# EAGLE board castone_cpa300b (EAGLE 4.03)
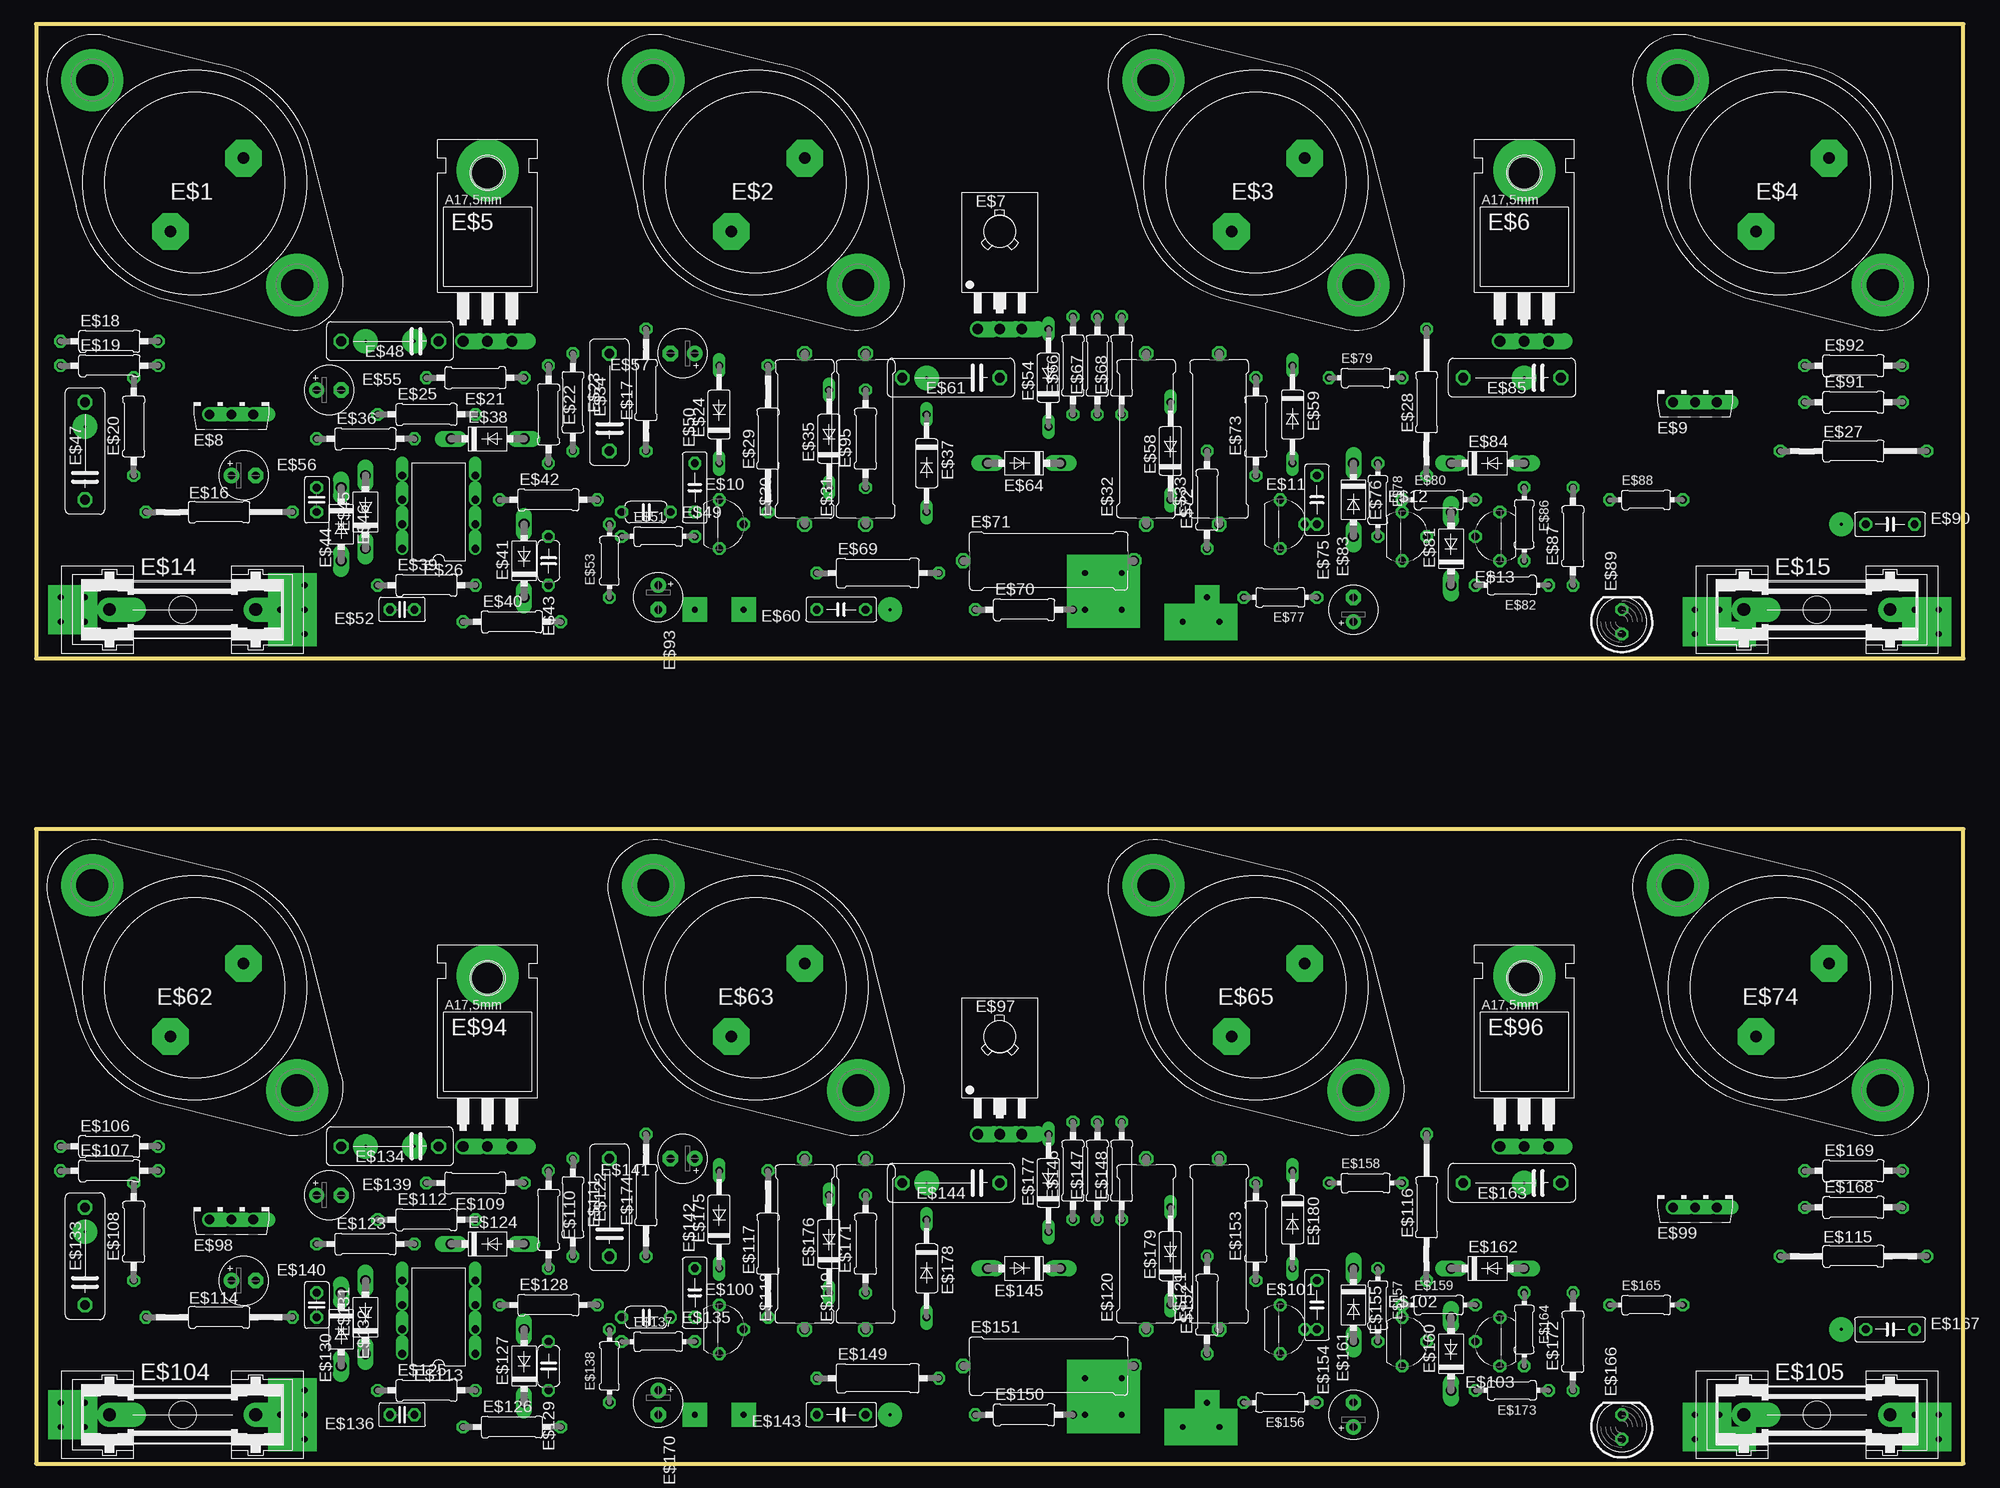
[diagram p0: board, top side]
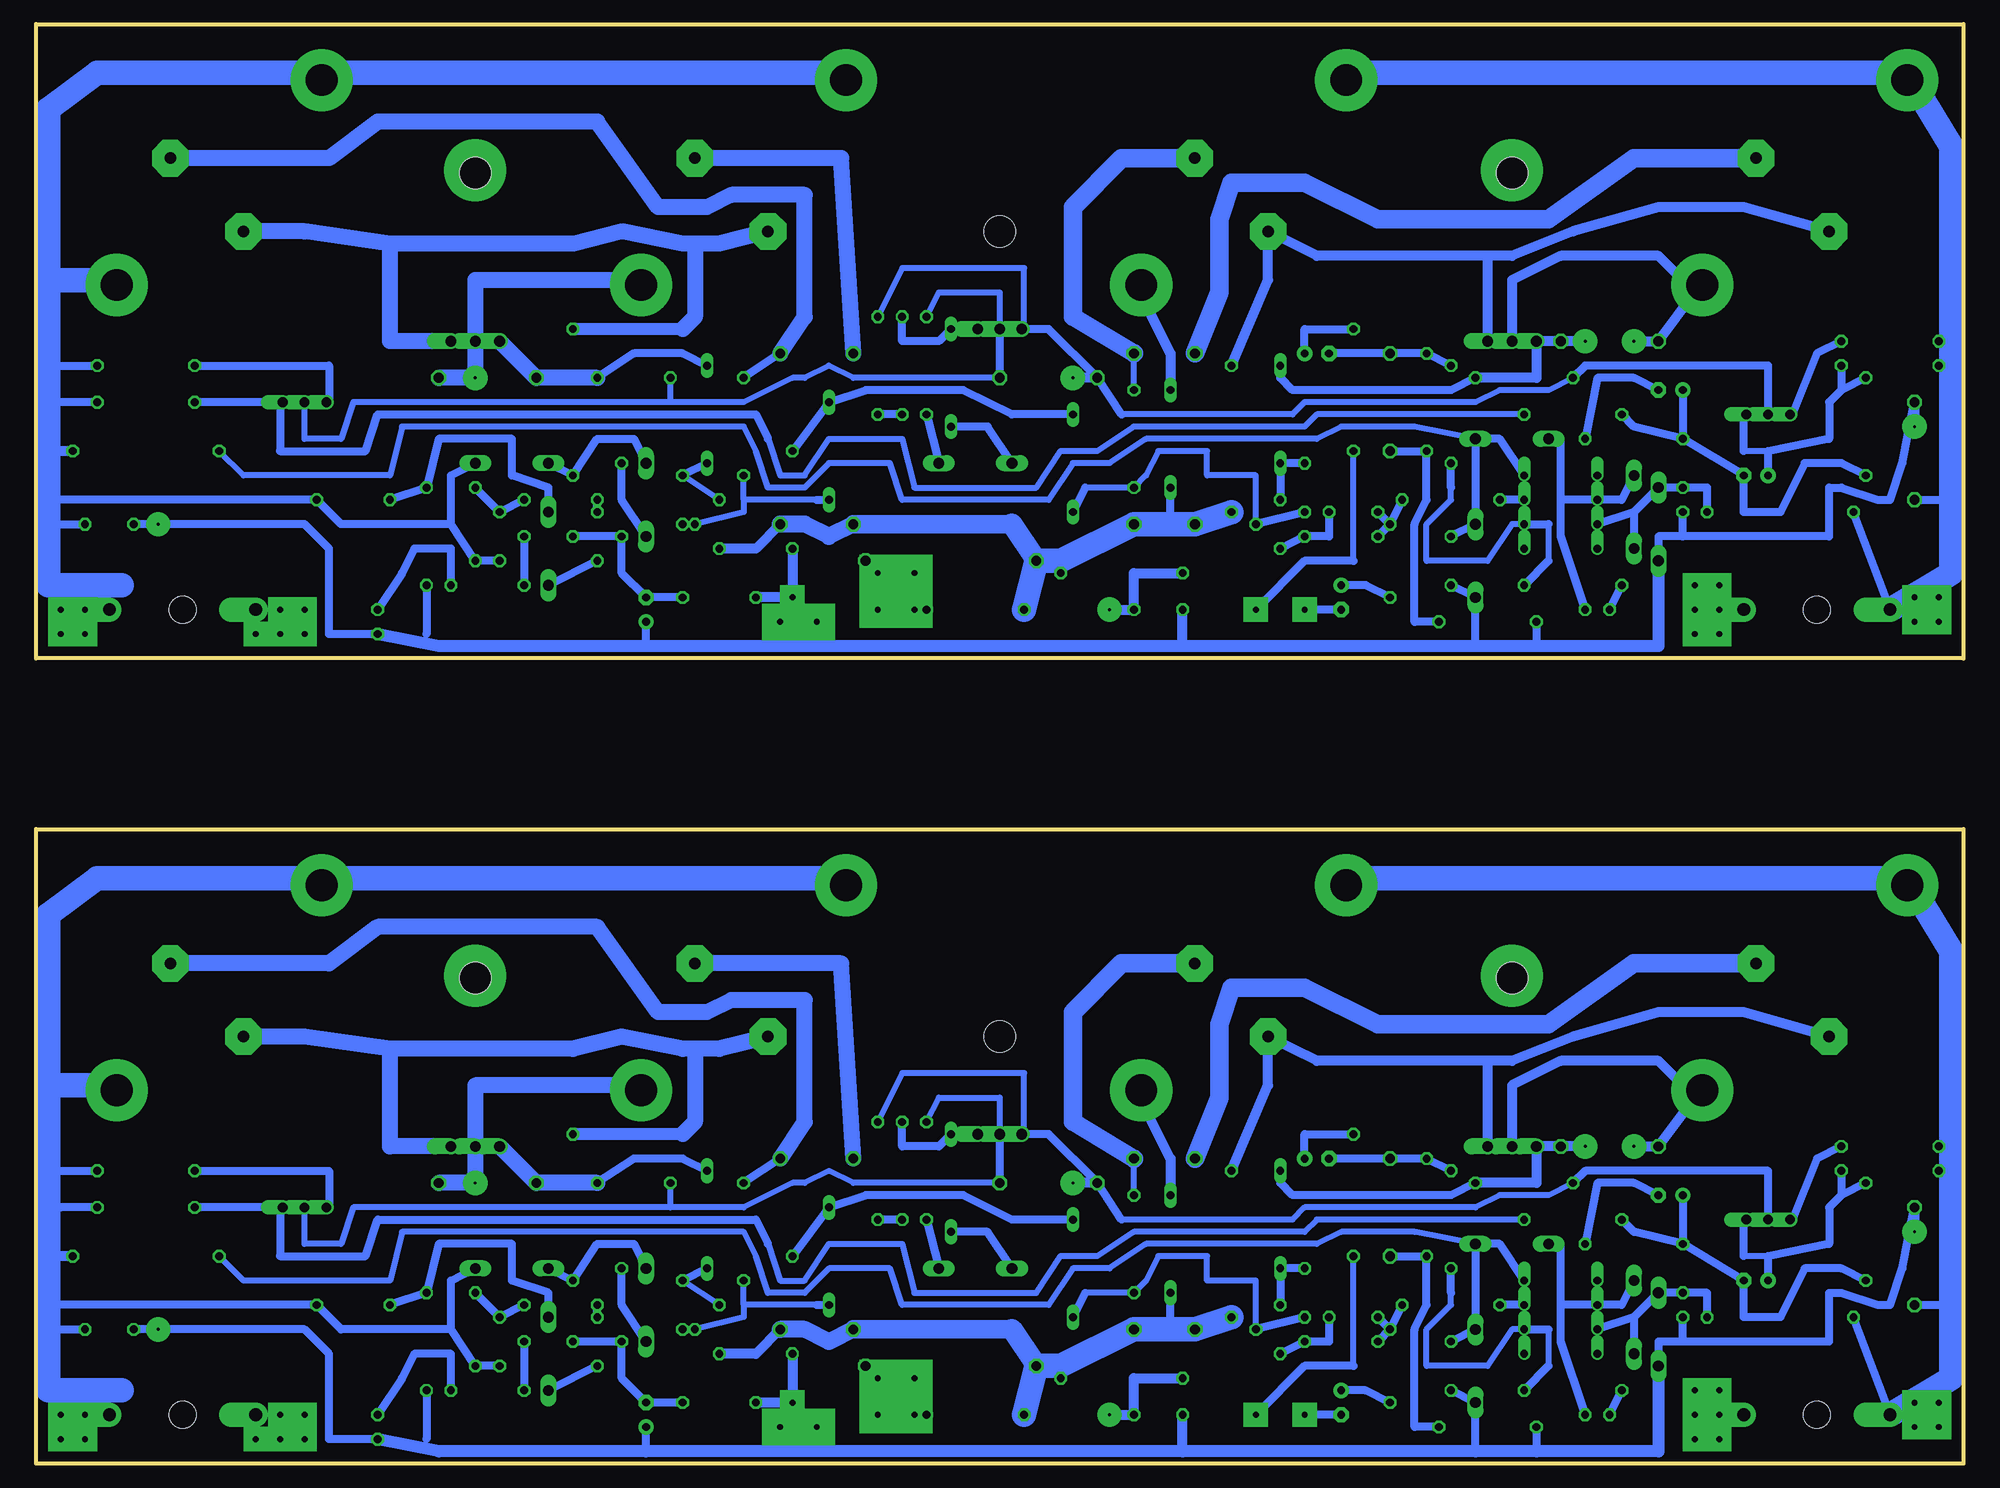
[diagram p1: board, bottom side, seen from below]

Size 200.66 x 149.86 mm. Coordinates in mm from the lower left corner, seen from the top.
Outline: 0,83.82 200.66,83.82 200.66,149.86 0,149.86 0,83.82
Outline: 0,0 200.66,0 200.66,66.04 0,66.04 0,0
Copper layers used: Bottom

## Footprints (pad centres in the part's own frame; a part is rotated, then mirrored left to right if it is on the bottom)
TO3/A = drill 1.194 pad 3.81 octagon: B 2.54,5.08; E -5.08,-2.54 | drill 3.302 pad 6.477 round: C 10.668,-10.668; C/ -10.668,10.668
TO220 = drill 1.118 offset: 1 -2.54,-6.35; 2 0,-6.35; 3 2.54,-6.35 | hole 3.302: 0,11.176
TO126 = drill 1.118 offset: 1 -2.286,-5.08; 2 0,-5.08; 3 2.286,-5.08 | hole 3.302: 0,5.08
TO126V = drill 1.016 offset: 1 -2.286,-1.27; 2 0,-1.27; 3 2.286,-1.27
TO92L = drill 0.813 octagon: 1 0,-2.54; 2 2.54,0; 3 0,2.54
GSH15 = drill 1.321 pad 2.54 offset: 1 -7.62,0; 2 7.62,0 | hole 2.794: 0,0
0207/15 = drill 0.813 octagon: 1 -7.62,0; 2 7.62,0
0207/12 = drill 0.813 octagon: 1 -6.35,0; 2 6.35,0
0207/10 = drill 0.813 octagon: 1 -5.08,0; 2 5.08,0
C2992 = drill 0.813 long: A 5.08,0; C -5.08,0
DIL08 = drill 0.813 offset: 1 -3.81,-3.81; 2 -1.27,-3.81; 3 1.27,-3.81; 4 3.81,-3.81; 5 3.81,3.81; 6 1.27,3.81; 7 -1.27,3.81; 8 -3.81,3.81
0617/17 = drill 1.016 octagon: 1 -8.89,0; 2 8.89,0
C102-043X133 = drill 1.016 octagon: 1 -5.08,0; 2 5.08,0
DO41-7 = drill 1.118 long: A 3.81,0; C -3.81,0
C050-024X044 = drill 0.813 octagon: 1 -2.54,0; 2 2.54,0
C025-025X050 = drill 0.813 octagon: 1 -1.27,0; 2 1.27,0
C050-025X075 = drill 0.813 octagon: 1 -2.54,0; 2 2.54,0
0204/7 = drill 0.813 octagon: 1 -3.81,0; 2 3.81,0
E2,5-5 = drill 0.813 pad 1.6 round: + -1.27,0 | drill 0.813 pad 1.6 octagon: - 1.27,0
0309/12 = drill 0.813 octagon: 1 -6.35,0; 2 6.35,0
LED5MM = drill 0.813 octagon: A -1.27,0; K 1.27,0

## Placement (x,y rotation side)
E$1  [TO3/A]  16.51,133.35 180 top
E$2  [TO3/A]  74.93,133.35 180 top
E$3  [TO3/A]  127,133.35 180 top
E$4  [TO3/A]  181.61,133.35 180 top
E$5  [TO220]  46.99,123.19 0 top
E$6  [TO220]  154.94,123.19 0 top
E$7  [TO126]  100.33,123.19 0 top
E$8  [TO126V]  20.32,110.49 0 top
E$9  [TO126V]  172.72,111.76 0 top
E$10  [TO92L]  71.12,97.79 0 top
E$11  [TO92L]  129.54,97.79 0 top
E$12  [TO92L]  142.24,96.52 0 top
E$13  [TO92L]  152.4,96.52 180 top
E$14  [GSH15]  15.24,88.9 0 top
E$15  [GSH15]  185.42,88.9 0 top
E$16  [0207/15]  19.05,99.06 0 top
E$17  [0207/12]  63.5,111.76 90 top
E$18  [0207/10]  7.62,116.84 0 top
E$19  [0207/10]  7.62,114.3 0 top
E$20  [0207/10]  10.16,107.95 90 top
E$21  [0207/10]  45.72,113.03 180 top
E$22  [0207/10]  53.34,109.22 270 top
E$23  [0207/10]  55.88,110.49 270 top
E$24  [C2992]  71.12,109.22 90 top
E$25  [0207/10]  40.64,109.22 0 top
E$26  [DIL08]  41.91,99.06 90 top
E$27  [0207/15]  189.23,105.41 0 top
E$28  [0207/15]  144.78,110.49 90 top
E$29  [0207/15]  76.2,106.68 90 top
E$30  [0617/17]  80.01,106.68 90 top
E$31  [0617/17]  86.36,106.68 90 top
E$32  [0617/17]  115.57,106.68 90 top
E$33  [0617/17]  123.19,106.68 90 top
E$34  [C102-043X133]  59.69,110.49 90 top
E$35  [C2992]  82.55,106.68 90 top
E$36  [0207/10]  34.29,106.68 0 top
E$37  [C2992]  92.71,104.14 270 top
E$38  [DO41-7]  46.99,106.68 0 top
E$39  [0207/10]  40.64,91.44 0 top
E$40  [0207/10]  49.53,87.63 0 top
E$41  [DO41-7]  50.8,93.98 90 top
E$42  [0207/10]  53.34,100.33 0 top
E$43  [C050-024X044]  53.34,93.98 270 top
E$44  [C025-025X050]  29.21,100.33 270 top
E$45  [DO41-7]  34.29,99.06 90 top
E$46  [DO41-7]  31.75,97.79 270 top
E$47  [C102-043X133]  5.08,105.41 90 top
E$48  [C102-043X133]  36.83,116.84 180 top
E$49  [C050-024X044]  63.5,99.06 0 top
E$50  [C050-025X075]  68.58,101.6 90 top
E$51  [0204/7]  64.77,96.52 0 top
E$52  [C025-025X050]  38.1,88.9 180 top
E$53  [0204/7]  59.69,93.98 90 top
E$54  [C2992]  105.41,113.03 90 top
E$55  [E2,5-5]  30.48,111.76 0 top
E$56  [E2,5-5]  21.59,102.87 0 top
E$57  [E2,5-5]  67.31,115.57 180 top
E$58  [C2992]  118.11,105.41 90 top
E$59  [C2992]  130.81,109.22 270 top
E$60  [C050-025X075]  83.82,88.9 180 top
E$61  [C102-043X133]  95.25,113.03 180 top
E$62  [TO3/A]  16.51,49.53 180 top
E$63  [TO3/A]  74.93,49.53 180 top
E$64  [DO41-7]  102.87,104.14 180 top
E$65  [TO3/A]  127,49.53 180 top
E$66  [0207/10]  107.95,114.3 90 top
E$67  [0207/10]  110.49,114.3 90 top
E$68  [0207/10]  113.03,114.3 90 top
E$69  [0309/12]  87.63,92.71 0 top
E$70  [0207/10]  102.87,88.9 0 top
E$71  [0617/17]  105.41,93.98 0 top
E$72  [0207/10]  121.92,100.33 90 top
E$73  [0207/10]  127,107.95 90 top
E$74  [TO3/A]  181.61,49.53 180 top
E$75  [C050-025X075]  133.35,100.33 270 top
E$76  [DO41-7]  137.16,100.33 270 top
E$77  [0204/7]  129.54,90.17 180 top
E$78  [0204/7]  139.7,100.33 270 top
E$79  [0204/7]  138.43,113.03 0 top
E$80  [0204/7]  146.05,100.33 0 top
E$81  [DO41-7]  147.32,95.25 90 top
E$82  [0204/7]  153.67,91.44 180 top
E$83  [E2,5-5]  137.16,88.9 90 top
E$84  [DO41-7]  151.13,104.14 0 top
E$85  [C102-043X133]  153.67,113.03 180 top
E$86  [0204/7]  154.94,97.79 270 top
E$87  [0207/10]  160.02,96.52 90 top
E$88  [0204/7]  167.64,100.33 0 top
E$89  [LED5MM]  165.1,87.63 90 top
E$90  [C050-025X075]  193.04,97.79 0 top
E$91  [0207/10]  189.23,110.49 0 top
E$92  [0207/10]  189.23,114.3 0 top
E$93  [E2,5-5]  64.77,90.17 270 top
E$94  [TO220]  46.99,39.37 0 top
E$95  [0207/10]  86.36,106.68 90 top
E$96  [TO220]  154.94,39.37 0 top
E$97  [TO126]  100.33,39.37 0 top
E$98  [TO126V]  20.32,26.67 0 top
E$99  [TO126V]  172.72,27.94 0 top
E$100  [TO92L]  71.12,13.97 0 top
E$101  [TO92L]  129.54,13.97 0 top
E$102  [TO92L]  142.24,12.7 0 top
E$103  [TO92L]  152.4,12.7 180 top
E$104  [GSH15]  15.24,5.08 0 top
E$105  [GSH15]  185.42,5.08 0 top
E$106  [0207/10]  7.62,33.02 0 top
E$107  [0207/10]  7.62,30.48 0 top
E$108  [0207/10]  10.16,24.13 90 top
E$109  [0207/10]  45.72,29.21 180 top
E$110  [0207/10]  53.34,25.4 270 top
E$111  [0207/10]  55.88,26.67 270 top
E$112  [0207/10]  40.64,25.4 0 top
E$113  [DIL08]  41.91,15.24 90 top
E$114  [0207/15]  19.05,15.24 0 top
E$115  [0207/15]  189.23,21.59 0 top
E$116  [0207/15]  144.78,26.67 90 top
E$117  [0207/15]  76.2,22.86 90 top
E$118  [0617/17]  80.01,22.86 90 top
E$119  [0617/17]  86.36,22.86 90 top
E$120  [0617/17]  115.57,22.86 90 top
E$121  [0617/17]  123.19,22.86 90 top
E$122  [C102-043X133]  59.69,26.67 90 top
E$123  [0207/10]  34.29,22.86 0 top
E$124  [DO41-7]  46.99,22.86 0 top
E$125  [0207/10]  40.64,7.62 0 top
E$126  [0207/10]  49.53,3.81 0 top
E$127  [DO41-7]  50.8,10.16 90 top
E$128  [0207/10]  53.34,16.51 0 top
E$129  [C050-024X044]  53.34,10.16 270 top
E$130  [C025-025X050]  29.21,16.51 270 top
E$131  [DO41-7]  34.29,15.24 90 top
E$132  [DO41-7]  31.75,13.97 270 top
E$133  [C102-043X133]  5.08,21.59 90 top
E$134  [C102-043X133]  36.83,33.02 180 top
E$135  [C050-024X044]  63.5,15.24 0 top
E$136  [C025-025X050]  38.1,5.08 180 top
E$137  [0204/7]  64.77,12.7 0 top
E$138  [0204/7]  59.69,10.16 90 top
E$139  [E2,5-5]  30.48,27.94 0 top
E$140  [E2,5-5]  21.59,19.05 0 top
E$141  [E2,5-5]  67.31,31.75 180 top
E$142  [C050-025X075]  68.58,17.78 90 top
E$143  [C050-025X075]  83.82,5.08 180 top
E$144  [C102-043X133]  95.25,29.21 180 top
E$145  [DO41-7]  102.87,20.32 180 top
E$146  [0207/10]  107.95,30.48 90 top
E$147  [0207/10]  110.49,30.48 90 top
E$148  [0207/10]  113.03,30.48 90 top
E$149  [0309/12]  87.63,8.89 0 top
E$150  [0207/10]  102.87,5.08 0 top
E$151  [0617/17]  105.41,10.16 0 top
E$152  [0207/10]  121.92,16.51 90 top
E$153  [0207/10]  127,24.13 90 top
E$154  [C050-025X075]  133.35,16.51 270 top
E$155  [DO41-7]  137.16,16.51 270 top
E$156  [0204/7]  129.54,6.35 180 top
E$157  [0204/7]  139.7,16.51 270 top
E$158  [0204/7]  138.43,29.21 0 top
E$159  [0204/7]  146.05,16.51 0 top
E$160  [DO41-7]  147.32,11.43 90 top
E$161  [E2,5-5]  137.16,5.08 90 top
E$162  [DO41-7]  151.13,20.32 0 top
E$163  [C102-043X133]  153.67,29.21 180 top
E$164  [0204/7]  154.94,13.97 270 top
E$165  [0204/7]  167.64,16.51 0 top
E$166  [LED5MM]  165.1,3.81 90 top
E$167  [C050-025X075]  193.04,13.97 0 top
E$168  [0207/10]  189.23,26.67 0 top
E$169  [0207/10]  189.23,30.48 0 top
E$170  [E2,5-5]  64.77,6.35 270 top
E$171  [0207/10]  86.36,22.86 90 top
E$172  [0207/10]  160.02,12.7 90 top
E$173  [0204/7]  153.67,7.62 180 top
E$174  [0207/12]  63.5,27.94 90 top
E$175  [C2992]  71.12,25.4 90 top
E$176  [C2992]  82.55,22.86 90 top
E$177  [C2992]  105.41,29.21 90 top
E$178  [C2992]  92.71,20.32 270 top
E$179  [C2992]  118.11,21.59 90 top
E$180  [C2992]  130.81,25.4 270 top

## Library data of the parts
E$1-E$13 E$62 E$63 E$65 E$74 E$94 E$96-E$103 = transistor-pnp
E$14 E$15 E$104 E$105 = fuse
E$16-E$23 E$25 E$27-E$34 E$36 E$39 E$40 E$42-E$44 E$47-E$53 E$55-E$57 E$60 E$61 E$66-E$73 E$75 E$77-E$80 E$82 E$83 E$85-E$88 E$90-E$93 E$95 E$106-E$112 E$114-E$123 E$125 E$126 E$128-E$130 E$133-E$144 E$146-E$154 E$156-E$159 E$161 E$163-E$165 E$167-E$174 = rcl
E$24 E$35 E$37 E$38 E$41 E$45 E$46 E$54 E$58 E$59 E$64 E$76 E$81 E$84 E$124 E$127 E$131 E$132 E$145 E$155 E$160 E$162 E$175-E$180 = diode
E$26 E$113 = dil
E$89 E$166 = led

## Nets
S$1: E$18.2
S$2: E$19.2 E$20.2 E$56.+
S$4: E$5.2 E$48.2
S$5: E$1.E E$30.2
S$6: E$35.A
S$7: E$2.E E$31.2 E$95.2
S$8: E$11.3 E$59.A E$75.1
S$9: E$16.2 E$26.7 E$44.1 E$45.C E$46.C
S$10: E$20.1 E$25.1 E$36.1 E$55.+ E$56.-
S$11: E$26.6 E$38.C E$45.A E$52.1
S$12: E$14.1 E$16.1 E$18.1 E$19.1 E$47.1
S$14: E$13.3 E$27.2 E$84.A E$86.2 E$88.2 E$90.2 E$92.2
S$15: E$40.1 E$41.C E$43.2 E$44.2 E$46.A E$47.2 E$60.2 E$83.+ E$89.A E$90.1
S$16: E$26.4 E$27.1 E$38.A E$41.A E$43.1
S$17: E$39.1 E$52.2
S$18: E$22.2 E$26.2 E$39.2
S$19: E$26.3 E$42.1
S$20: E$25.2 E$91.1
S$21: E$36.2 E$55.-
S$22: E$22.1 E$23.1 E$34.2 E$57.-
S$23: E$106.2
S$24: E$23.2 E$34.1 E$40.2
S$25: E$42.2 E$49.1 E$51.1 E$53.2
S$26: E$10.1 E$49.2 E$51.2
S$27: E$53.1 E$93.+
S$28: E$93.-
S$29: E$17.1
S$30: E$60.1 E$69.1
S$31: E$10.3 E$24.C E$50.2
S$32: E$10.2 E$37.A E$50.1 E$95.1
S$33: E$17.2 E$57.+
S$34: E$11.1 E$29.1 E$30.1 E$31.1 E$32.1 E$33.1 E$35.C E$69.2 E$70.1 E$71.1
S$35: E$107.2 E$108.2 E$140.+
S$37: E$54.C E$64.A
S$38: E$72.1 E$77.2
S$39: E$54.A E$67.2
S$40: E$67.1 E$68.1
S$41: E$64.C E$66.1
S$42: E$3.E E$32.2
S$43: E$4.E E$33.2 E$73.2
S$44: E$3.B E$4.B E$28.2
S$45: E$6.2 E$85.1
S$46: E$6.1 E$59.C E$79.2 E$85.2
S$47: E$6.3
S$48: E$7.2 E$9.2 E$61.1 E$66.2 E$79.1
S$49: E$87.1
S$50: E$37.C E$58.A E$72.2
S$51: E$8.2 E$21.2 E$61.2 E$68.2
S$52: E$28.1 E$76.C E$84.C
S$53: E$11.2 E$58.C E$73.1 E$75.2
S$54: E$12.2 E$77.1 E$78.2 E$83.-
S$55: E$12.3 E$80.1
S$56: E$13.1 E$80.2 E$86.1
S$58: E$12.1 E$81.C
S$59: E$81.A E$87.2 E$88.1
S$60: E$13.2 E$82.2
S$61: E$82.1 E$89.K
S$62: E$91.2
S$63: E$92.1
S$64: E$1.B E$2.B E$5.3 E$29.2
S$81: E$76.A E$78.1
S$90: E$62.E E$118.2
S$91: E$176.A
S$92: E$63.E E$119.2 E$171.2
S$93: E$5.1 E$21.1 E$24.A E$48.1
S$94: E$108.1 E$112.1 E$123.1 E$139.+ E$140.-
S$95: E$104.1 E$106.1 E$107.1 E$114.1 E$133.1
S$97: E$126.1 E$127.C E$129.2 E$130.2 E$132.A E$133.2 E$143.2 E$161.+ E$166.A E$167.1
S$98: E$113.7 E$114.2 E$130.1 E$131.C E$132.C
S$99: E$113.6 E$124.C E$131.A E$136.1
S$100: E$125.1 E$136.2
S$101: E$110.2 E$113.2 E$125.2
S$102: E$113.3 E$128.1
S$103: E$123.2 E$139.-
S$104: E$110.1 E$111.1 E$122.2 E$141.-
S$105: E$112.2 E$168.1
S$106: E$111.2 E$122.1 E$126.2
S$107: E$128.2 E$135.1 E$137.1 E$138.2
S$108: E$100.1 E$135.2 E$137.2
S$109: E$138.1 E$170.+
S$110: E$170.-
S$111: E$174.1
S$112: E$141.+ E$174.2
S$113: E$101.1 E$117.1 E$118.1 E$119.1 E$120.1 E$121.1 E$149.2 E$150.1 E$151.1 E$176.C
S$114: E$152.1 E$156.2
S$115: E$100.2 E$142.1 E$171.1 E$178.A
S$116: E$143.1 E$149.1
S$117: E$145.A E$177.C
S$118: E$147.1 E$148.1
S$119: E$145.C E$146.1
S$120: E$65.E E$120.2
S$121: E$74.E E$121.2 E$153.2
S$122: E$65.B E$74.B E$116.2
S$123: E$96.2 E$163.1
S$124: E$96.1 E$158.2 E$163.2 E$180.C
S$125: E$96.3
S$126: E$97.2 E$99.2 E$144.1 E$146.2 E$158.1
S$127: E$101.2 E$153.1 E$154.2 E$179.C
S$128: E$101.3 E$154.1 E$180.A
S$129: E$116.1 E$155.C E$162.C
S$130: E$102.2 E$156.1 E$157.2 E$161.-
S$131: E$102.3 E$159.1
S$132: E$103.1 E$159.2 E$164.1
S$133: E$102.1 E$160.C
S$134: E$160.A E$165.1 E$172.2
S$135: E$103.2 E$173.2
S$136: E$166.K E$173.1
S$137: E$103.3 E$115.2 E$162.A E$164.2 E$165.2 E$167.2 E$169.2
S$138: E$168.2
S$139: E$169.1
S$151: E$98.2 E$109.2 E$144.2 E$148.2
S$152: E$94.2 E$134.2
S$153: E$62.B E$63.B E$94.3 E$117.2
S$162: E$155.A E$157.1
S$163: E$172.1
S$164: E$100.3 E$142.2 E$175.C
S$165: E$147.2 E$177.A
S$166: E$152.2 E$178.C E$179.A
S$167: E$113.4 E$115.1 E$124.A E$127.A E$129.1
S$176: E$94.1 E$109.1 E$134.1 E$175.A

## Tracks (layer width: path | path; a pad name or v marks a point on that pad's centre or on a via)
S$1
  Bottom 0.813: E$18.2 15.24,115.57 17.78,109.22
S$2
  Bottom 0.61: 20.32,105.41 22.86,105.41
  Bottom 0.813: E$20.2 12.7,111.76 | 12.7,111.76 13.97,110.49 13.97,106.68 20.32,105.41 E$56.+ | 22.86,105.41 22.86,109.22 | E$19.2 12.7,111.76
S$3  (via drill 0.61 pad 3.81)
  other vias: 119.38,87.63
S$4  (via drill 0.3 pad 2.54)
  Bottom 1.016: E$5.2 46.99,123.19 41.91,125.73 31.75,125.73 27.94,121.92 E$48.2 v34.29,116.84
S$5
  Bottom 1.93: E$1.E 34.29,135.89 43.18,129.54 60.96,129.54 68.58,133.35 76.2,133.35 77.47,129.54 77.47,121.92 E$30.2
S$6
  Bottom 0.813: 85.09,120.65 85.09,123.19
  Bottom 1.016: 85.09,120.65 82.55,115.57 E$35.A
S$7
  Bottom 0.61: E$95.2 E$31.2
  Bottom 1.93: E$2.E 87.63,135.89 92.71,130.81 92.71,119.38 E$31.2
S$8
  Bottom 0.61: E$11.3 E$75.1
  Bottom 0.813: E$59.A E$75.1
S$9
  Bottom 0.813: E$16.2 26.67,101.6 E$44.1 E$46.C 34.29,99.06 | 34.29,99.06 E$26.7 | 34.29,99.06 E$45.C
S$10
  Bottom 0.813: E$36.1 E$56.- 22.86,99.06 19.05,99.06 16.51,104.14 12.7,104.14 E$20.1 | E$55.+ E$36.1 | E$36.1 34.29,107.95 E$25.1
S$11
  Bottom 0.813: E$45.A 35.56,100.33 E$26.6 41.91,100.33 | 41.91,100.33 41.91,106.68 E$38.C | E$52.1 41.91,96.52 41.91,100.33
S$12
  Bottom 0.813: E$47.1 1.27,100.33 | E$16.1 E$14.1
  Bottom 1.27: E$18.1 1.27,116.84 | E$19.1 1.27,114.3
  Bottom 2.54: E$14.1 1.27,92.71 1.27,100.33 1.27,114.3 1.27,116.84 1.27,137.16 5.08,143.51
S$13
  Bottom 2.54: 6.35,144.78 64.77,144.78
S$14
  Bottom 0.813: E$84.A 157.48,102.87 157.48,97.79 | 157.48,97.79 168.91,97.79 E$88.2 199.39,100.33 | 157.48,97.79 E$86.2 E$13.3 | 199.39,97.79 E$90.2 | 199.39,114.3 E$92.2
  Bottom 1.016: E$27.2 199.39,105.41
  Bottom 2.54: 191.77,91.44 199.39,91.44 199.39,97.79 199.39,100.33 199.39,105.41 199.39,114.3 199.39,123.19 | 199.39,123.19 199.39,140.97 194.31,144.78 116.84,144.78 | 191.77,123.19 199.39,123.19
S$15  (via drill 0.3 pad 2.54)
  Bottom 0.813: 29.21,96.52 E$44.2 | 29.21,96.52 31.75,96.52 E$46.A | E$47.2 6.35,104.14 7.62,100.33 8.89,100.33 12.7,101.6 13.97,101.6 13.97,96.52 29.21,96.52 | 50.8,85.09 E$41.C E$43.2 | 137.16,85.09 E$83.+ | E$89.A 170.18,86.36 170.18,95.25 172.72,97.79 v187.96,97.79 E$90.1 | E$40.1 44.45,85.09
  Bottom 1.016: 81.28,85.09 E$60.2 | E$47.2 v5.08,107.95
  Bottom 1.27: E$89.A 158.75,85.09 137.16,85.09 81.28,85.09 50.8,85.09 44.45,85.09 31.75,85.09 E$46.A
S$16
  Bottom 0.61: E$38.A 57.15,107.95 64.77,107.95 67.31,106.68 85.09,106.68 88.9,104.14 92.71,104.14 95.25,100.33 110.49,100.33 111.76,104.14 118.11,104.14 120.65,101.6 124.46,101.6 125.73,105.41 127,107.95 162.56,107.95 163.83,102.87 179.07,102.87 E$27.1
  Bottom 0.813: E$43.1 E$41.A E$38.A 48.26,106.68 E$26.4
S$17
  Bottom 0.813: E$52.2 E$39.1
S$18
  Bottom 0.61: 43.18,97.79 43.18,93.98 | E$26.2 46.99,97.79 49.53,93.98 55.88,93.98 55.88,97.79 53.34,100.33 53.34,101.6
  Bottom 0.813: E$26.2 43.18,97.79 | 43.18,93.98 E$39.2 | 53.34,101.6 E$22.2
S$19
  Bottom 0.813: E$26.3 E$42.1
S$20
  Bottom 0.61: E$25.2 67.31,109.22 68.58,107.95 86.36,107.95 90.17,105.41 93.98,105.41 96.52,101.6 109.22,101.6 110.49,106.68 118.11,106.68 120.65,102.87 123.19,102.87 124.46,106.68
  Bottom 0.813: E$91.1 175.26,110.49 175.26,105.41 166.37,105.41 165.1,109.22 125.73,109.22 124.46,106.68
S$21
  Bottom 0.813: E$55.- 34.29,113.03 38.1,113.03 E$36.2
S$22
  Bottom 0.813: E$22.1 E$23.1 E$34.2 E$57.-
S$23
  Bottom 0.813: E$106.2 15.24,31.75 17.78,25.4
S$24
  Bottom 0.813: E$40.2 57.15,87.63 57.15,97.79 55.88,100.33 E$23.2 E$34.1
S$25
  Bottom 0.813: E$42.2 E$53.2 | E$53.2 E$49.1 | E$53.2 E$51.1
S$26
  Bottom 0.813: E$49.2 66.04,96.52 E$51.2 E$10.1
S$27
  Bottom 0.813: E$53.1 62.23,91.44 E$93.+
S$28  (via drill 0.61 pad 2.54)
  Bottom 0.813: E$93.- v68.58,88.9
S$29  (via drill 0.61 pad 2.54)
  Bottom 0.61: 63.5,93.98 E$17.1
  Bottom 0.813: 63.5,93.98 68.58,93.98 v73.66,88.9
S$30  (via drill 0.3 pad 2.54)
  Bottom 1.016: E$69.1 86.36,92.71 E$60.1 v88.9,88.9
S$31
  Bottom 0.813: E$50.2 E$24.C E$10.3
S$32
  Bottom 0.61: 91.44,101.6 E$95.1 85.09,102.87 83.82,105.41 78.74,105.41 78.74,102.87 73.66,102.87 E$10.2
  Bottom 0.813: E$50.1 E$10.2 | 91.44,101.6 E$37.A
S$33
  Bottom 0.813: E$57.+ 68.58,118.11 E$17.2
S$34
  Bottom 0.813: 82.55,97.79 E$35.C
  Bottom 1.016: 93.98,93.98 E$69.2 | E$33.1 125.73,95.25 E$11.1
  Bottom 1.778: E$32.1 118.11,96.52 120.65,97.79 E$33.1
  Bottom 1.93: 99.06,97.79 E$32.1
  Bottom 2.184: E$71.1 99.06,97.79
  Bottom 2.54: E$29.1 E$30.1 82.55,97.79 E$31.1 93.98,93.98 E$71.1 E$70.1
S$35
  Bottom 0.61: 20.32,21.59 22.86,21.59
  Bottom 0.813: E$108.2 12.7,27.94 | 12.7,27.94 13.97,26.67 13.97,22.86 20.32,21.59 E$140.+ | 22.86,21.59 22.86,25.4 | E$107.2 12.7,27.94
S$36  (via drill 0.61 pad 3.81)
  other vias: 109.22,88.9
S$37
  Bottom 0.813: E$64.A 101.6,107.95 E$54.C
S$38  (via drill 0.61 pad 2.54)
  Bottom 1.016: E$77.2 v121.92,90.17 E$72.1
S$39
  Bottom 0.813: E$67.2 110.49,116.84 106.68,116.84 E$54.A 102.87,118.11
S$40
  Bottom 0.813: E$67.1 E$68.1
S$41
  Bottom 0.813: E$66.1 E$64.C
S$42
  Bottom 1.676: E$32.2 116.84,135.89 E$3.E
S$43
  Bottom 0.813: E$33.2 E$73.2
  Bottom 1.676: E$33.2 120.65,119.38 120.65,132.08 128.27,132.08 130.81,130.81 135.89,130.81 142.24,139.7 165.1,139.7 170.18,135.89 E$4.E
S$44
  Bottom 1.27: 133.35,118.11 E$28.2
  Bottom 1.676: E$3.B 129.54,127 132.08,127 | 132.08,127 133.35,127 139.7,128.27 144.78,127 163.83,127 172.72,128.27 E$4.B | 132.08,127 132.08,119.38 133.35,118.11
S$45  (via drill 0.3 pad 2.54)
  Bottom 1.676: 138.43,123.19 154.94,123.19 E$6.2 v154.94,113.03 E$85.1
S$46
  Bottom 0.813: E$79.2 138.43,115.57 133.35,115.57 E$59.C
  Bottom 1.676: E$79.2 E$85.2 E$6.1
S$47
  Bottom 1.676: E$6.3 163.83,116.84 163.83,127
S$48
  Bottom 0.61: E$61.1 115.57,113.03 118.11,114.3 120.65,113.03 121.92,113.03 127,110.49 134.62,110.49 | 134.62,110.49 E$79.1 | 134.62,110.49 167.64,110.49 168.91,106.68 172.72,106.68 E$9.2 | E$66.2 106.68,121.92 100.33,121.92 E$7.2
  Bottom 0.813: E$7.2 E$61.1
S$49
  Bottom 0.813: E$87.1 160.02,86.36
S$50
  Bottom 0.813: E$37.C 99.06,109.22 104.14,111.76 114.3,111.76 E$58.A E$72.2
S$51  (via drill 0.3 pad 2.54)
  Bottom 0.61: E$68.2 110.49,124.46 97.79,124.46 97.79,118.11 | 87.63,109.22 69.85,109.22 68.58,110.49 50.8,110.49 48.26,111.76 43.18,111.76 E$21.2
  Bottom 0.813: 97.79,118.11 95.25,118.11 E$61.2 87.63,109.22 | E$21.2 39.37,114.3 20.32,114.3 E$8.2
  Bottom 1.016: E$61.2 v92.71,113.03
S$52
  Bottom 0.813: E$84.C E$28.1 142.24,106.68 138.43,106.68 E$76.C
S$53
  Bottom 0.61: 127,100.33 E$73.1 | 127,100.33 127,99.06 E$11.2 E$75.2 | 119.38,100.33 127,100.33
  Bottom 0.813: 119.38,100.33 E$58.C
S$54
  Bottom 0.813: E$77.1 E$83.- 139.7,92.71 E$78.2 E$12.2
S$55
  Bottom 0.813: E$12.3 E$80.1
S$56
  Bottom 0.813: E$80.2 E$13.1 E$86.1
S$57  (via drill 0.61 pad 3.81)
  other vias: 123.19,87.63
S$58
  Bottom 0.813: E$12.1 E$81.C
S$59
  Bottom 0.813: E$81.A 147.32,101.6 151.13,102.87 151.13,106.68 158.75,106.68 E$87.2 E$88.1
S$60
  Bottom 0.813: E$13.2 E$82.2
S$61
  Bottom 0.813: E$82.1 157.48,95.25 161.29,95.25 162.56,92.71 E$89.K
S$62
  Bottom 0.813: E$91.2 198.12,110.49
S$63
  Bottom 0.813: E$92.1 170.18,114.3 170.18,110.49
S$64
  Bottom 1.016: E$29.2 72.39,123.19 E$2.B 67.31,125.73 49.53,125.73 | E$1.B 22.86,130.81 31.75,130.81 40.64,128.27 46.99,125.73 49.53,125.73 | 49.53,125.73 E$5.3
S$65  (via drill 0.61 pad 2.54)
  other vias: 175.26,88.9
S$66  (via drill 0.61 pad 2.54)
  other vias: 172.72,88.9
S$67  (via drill 0.61 pad 2.54)
  other vias: 172.72,86.36
S$68  (via drill 0.61 pad 2.54)
  other vias: 175.26,86.36
S$69  (via drill 0.61 pad 2.54)
  other vias: 177.8,86.36
S$70  (via drill 0.61 pad 2.54)
  other vias: 25.4,91.44
S$71  (via drill 0.61 pad 2.54)
  other vias: 25.4,88.9
S$72  (via drill 0.61 pad 2.54)
  other vias: 25.4,86.36
S$73  (via drill 0.61 pad 2.54)
  other vias: 27.94,91.44
S$74  (via drill 0.61 pad 2.54)
  other vias: 27.94,88.9
S$75  (via drill 0.61 pad 2.54)
  other vias: 27.94,86.36
S$76  (via drill 0.61 pad 3.81)
  other vias: 113.03,88.9
S$77  (via drill 0.61 pad 6.45)
  other vias: 154.94,134.62
S$78  (via drill 0.61 pad 6.45)
  other vias: 46.99,134.62
S$79  (via drill 0.61 pad 3.81)
  other vias: 113.03,92.71
S$80  (via drill 0.61 pad 3.81)
  other vias: 109.22,92.71
S$81
  Bottom 0.813: E$76.A 139.7,100.33 E$78.1
S$82  (via drill 0.61 pad 2.54)
  other vias: 5.08,90.17
S$83  (via drill 0.61 pad 2.54)
  other vias: 2.54,90.17
S$84  (via drill 0.61 pad 2.54)
  other vias: 5.08,87.63
S$85  (via drill 0.61 pad 2.54)
  other vias: 2.54,87.63
S$86  (via drill 0.61 pad 2.54)
  other vias: 195.58,88.9
S$87  (via drill 0.61 pad 2.54)
  other vias: 198.12,88.9
S$88  (via drill 0.61 pad 2.54)
  other vias: 195.58,86.36
S$89  (via drill 0.61 pad 2.54)
  other vias: 198.12,86.36
S$90
  Bottom 1.93: E$62.E 34.29,52.07 43.18,45.72 60.96,45.72 68.58,49.53 76.2,49.53 77.47,45.72 77.47,38.1 E$118.2
S$91
  Bottom 0.813: 85.09,36.83 85.09,39.37
  Bottom 1.016: 85.09,36.83 82.55,31.75 E$176.A
S$92
  Bottom 0.61: E$171.2 E$119.2
  Bottom 1.93: E$63.E 87.63,52.07 92.71,46.99 92.71,35.56 E$119.2
S$93  (via drill 0.3 pad 2.54)
  Bottom 0.813: E$21.1 53.34,111.76 69.85,111.76 71.12,113.03 E$24.A
  Bottom 1.016: E$21.1 44.45,113.03 E$5.1 E$48.1 v39.37,116.84
S$94
  Bottom 0.813: E$123.1 E$140.- 22.86,15.24 19.05,15.24 16.51,20.32 12.7,20.32 E$108.1 | E$139.+ E$123.1 | E$123.1 34.29,24.13 E$112.1
S$95
  Bottom 0.813: E$133.1 1.27,16.51 | E$114.1 E$104.1
  Bottom 1.27: E$106.1 1.27,33.02 | E$107.1 1.27,30.48
  Bottom 2.54: E$104.1 1.27,8.89 1.27,16.51 1.27,30.48 1.27,33.02 1.27,53.34 5.08,59.69
S$96
  Bottom 2.54: 6.35,60.96 64.77,60.96
S$97  (via drill 0.3 pad 2.54)
  Bottom 0.813: 29.21,12.7 E$130.2 | 29.21,12.7 31.75,12.7 E$132.A | E$133.2 6.35,20.32 7.62,16.51 8.89,16.51 12.7,17.78 13.97,17.78 13.97,12.7 29.21,12.7 | 50.8,1.27 E$127.C E$129.2 | 137.16,1.27 E$161.+ | E$166.A 170.18,2.54 170.18,11.43 172.72,13.97 v187.96,13.97 E$167.1 | E$126.1 44.45,1.27
  Bottom 1.016: 81.28,1.27 E$143.2 | E$133.2 v5.08,24.13
  Bottom 1.27: E$166.A 158.75,1.27 137.16,1.27 81.28,1.27 50.8,1.27 44.45,1.27 31.75,1.27 E$132.A
S$98
  Bottom 0.813: E$114.2 26.67,17.78 E$130.1 E$132.C 34.29,15.24 | 34.29,15.24 E$113.7 | 34.29,15.24 E$131.C
S$99
  Bottom 0.813: E$131.A 35.56,16.51 E$113.6 41.91,16.51 | 41.91,16.51 41.91,22.86 E$124.C | E$136.1 41.91,12.7 41.91,16.51
S$100
  Bottom 0.813: E$136.2 E$125.1
S$101
  Bottom 0.61: 43.18,13.97 43.18,10.16 | E$113.2 46.99,13.97 49.53,10.16 55.88,10.16 55.88,13.97 53.34,16.51 53.34,17.78
  Bottom 0.813: E$113.2 43.18,13.97 | 43.18,10.16 E$125.2 | 53.34,17.78 E$110.2
S$102
  Bottom 0.813: E$113.3 E$128.1
S$103
  Bottom 0.813: E$139.- 34.29,29.21 38.1,29.21 E$123.2
S$104
  Bottom 0.813: E$110.1 E$111.1 E$122.2 E$141.-
S$105
  Bottom 0.61: E$112.2 67.31,25.4 68.58,24.13 86.36,24.13 90.17,21.59 93.98,21.59 96.52,17.78 109.22,17.78 110.49,22.86 118.11,22.86 120.65,19.05 123.19,19.05 124.46,22.86
  Bottom 0.813: E$168.1 175.26,26.67 175.26,21.59 166.37,21.59 165.1,25.4 125.73,25.4 124.46,22.86
S$106
  Bottom 0.813: E$126.2 57.15,3.81 57.15,13.97 55.88,16.51 E$111.2 E$122.1
S$107
  Bottom 0.813: E$128.2 E$138.2 | E$138.2 E$135.1 | E$138.2 E$137.1
S$108
  Bottom 0.813: E$135.2 66.04,12.7 E$137.2 E$100.1
S$109
  Bottom 0.813: E$138.1 62.23,7.62 E$170.+
S$110  (via drill 0.61 pad 2.54)
  Bottom 0.813: E$170.- v68.58,5.08
S$111  (via drill 0.61 pad 2.54)
  Bottom 0.61: 63.5,10.16 E$174.1
  Bottom 0.813: 63.5,10.16 68.58,10.16 v73.66,5.08
S$112
  Bottom 0.813: E$141.+ 68.58,34.29 E$174.2
S$113
  Bottom 0.813: 82.55,13.97 E$176.C
  Bottom 1.016: 93.98,10.16 E$149.2 | E$121.1 125.73,11.43 E$101.1
  Bottom 1.778: E$120.1 118.11,12.7 120.65,13.97 E$121.1
  Bottom 1.93: 99.06,13.97 E$120.1
  Bottom 2.184: E$151.1 99.06,13.97
  Bottom 2.54: E$117.1 E$118.1 82.55,13.97 E$119.1 93.98,10.16 E$151.1 E$150.1
S$114  (via drill 0.61 pad 2.54)
  Bottom 1.016: E$156.2 v121.92,6.35 E$152.1
S$115
  Bottom 0.61: 91.44,17.78 E$171.1 85.09,19.05 83.82,21.59 78.74,21.59 78.74,19.05 73.66,19.05 E$100.2
  Bottom 0.813: E$142.1 E$100.2 | 91.44,17.78 E$178.A
S$116  (via drill 0.3 pad 2.54)
  Bottom 1.016: E$149.1 86.36,8.89 E$143.1 v88.9,5.08
S$117
  Bottom 0.813: E$145.A 101.6,24.13 E$177.C
S$118
  Bottom 0.813: E$147.1 E$148.1
S$119
  Bottom 0.813: E$146.1 E$145.C
S$120
  Bottom 1.676: E$120.2 116.84,52.07 E$65.E
S$121
  Bottom 0.813: E$121.2 E$153.2
  Bottom 1.676: E$121.2 120.65,35.56 120.65,48.26 128.27,48.26 130.81,46.99 135.89,46.99 142.24,55.88 165.1,55.88 170.18,52.07 E$74.E
S$122
  Bottom 1.27: 133.35,34.29 E$116.2
  Bottom 1.676: E$65.B 129.54,43.18 132.08,43.18 | 132.08,43.18 133.35,43.18 139.7,44.45 144.78,43.18 163.83,43.18 172.72,44.45 E$74.B | 132.08,43.18 132.08,35.56 133.35,34.29
S$123  (via drill 0.3 pad 2.54)
  Bottom 1.676: 138.43,39.37 154.94,39.37 E$96.2 v154.94,29.21 E$163.1
S$124
  Bottom 0.813: E$158.2 138.43,31.75 133.35,31.75 E$180.C
  Bottom 1.676: E$158.2 E$163.2 E$96.1
S$125
  Bottom 1.676: E$96.3 163.83,33.02 163.83,43.18
S$126
  Bottom 0.61: E$144.1 115.57,29.21 118.11,30.48 120.65,29.21 121.92,29.21 127,26.67 134.62,26.67 | 134.62,26.67 E$158.1 | 134.62,26.67 167.64,26.67 168.91,22.86 172.72,22.86 E$99.2 | E$146.2 106.68,38.1 100.33,38.1 E$97.2
  Bottom 0.813: E$97.2 E$144.1
S$127
  Bottom 0.61: 127,16.51 E$153.1 | 127,16.51 127,15.24 E$101.2 E$154.2 | 119.38,16.51 127,16.51
  Bottom 0.813: 119.38,16.51 E$179.C
S$128
  Bottom 0.61: E$101.3 E$154.1
  Bottom 0.813: E$180.A E$154.1
S$129
  Bottom 0.813: E$162.C E$116.1 142.24,22.86 138.43,22.86 E$155.C
S$130
  Bottom 0.813: E$156.1 E$161.- 139.7,8.89 E$157.2 E$102.2
S$131
  Bottom 0.813: E$102.3 E$159.1
S$132
  Bottom 0.813: E$159.2 E$103.1 E$164.1
S$133
  Bottom 0.813: E$102.1 E$160.C
S$134
  Bottom 0.813: E$160.A 147.32,17.78 151.13,19.05 151.13,22.86 158.75,22.86 E$172.2 E$165.1
S$135
  Bottom 0.813: E$103.2 E$173.2
S$136
  Bottom 0.813: E$173.1 157.48,11.43 161.29,11.43 162.56,8.89 E$166.K
S$137
  Bottom 0.813: E$162.A 157.48,19.05 157.48,13.97 | 157.48,13.97 168.91,13.97 E$165.2 199.39,16.51 | 157.48,13.97 E$164.2 E$103.3 | 199.39,13.97 E$167.2 | 199.39,30.48 E$169.2
  Bottom 1.016: E$115.2 199.39,21.59
  Bottom 2.54: 191.77,7.62 199.39,7.62 199.39,13.97 199.39,16.51 199.39,21.59 199.39,30.48 199.39,39.37 | 199.39,39.37 199.39,57.15 194.31,60.96 116.84,60.96 | 191.77,39.37 199.39,39.37
S$138
  Bottom 0.813: E$168.2 198.12,26.67
S$139
  Bottom 0.813: E$169.1 170.18,30.48 170.18,26.67
S$140  (via drill 0.61 pad 2.54)
  other vias: 175.26,5.08
S$141  (via drill 0.61 pad 2.54)
  other vias: 172.72,5.08
S$142  (via drill 0.61 pad 2.54)
  other vias: 172.72,2.54
S$143  (via drill 0.61 pad 2.54)
  other vias: 175.26,2.54
S$144  (via drill 0.61 pad 2.54)
  other vias: 177.8,2.54
S$145  (via drill 0.61 pad 2.54)
  other vias: 25.4,7.62
S$146  (via drill 0.61 pad 2.54)
  other vias: 25.4,5.08
S$147  (via drill 0.61 pad 2.54)
  other vias: 25.4,2.54
S$148  (via drill 0.61 pad 2.54)
  other vias: 27.94,7.62
S$149  (via drill 0.61 pad 2.54)
  other vias: 27.94,5.08
S$150  (via drill 0.61 pad 2.54)
  other vias: 27.94,2.54
S$151  (via drill 0.3 pad 2.54)
  Bottom 0.61: E$148.2 110.49,40.64 97.79,40.64 97.79,34.29 | 87.63,25.4 69.85,25.4 68.58,26.67 50.8,26.67 48.26,27.94 43.18,27.94 E$109.2
  Bottom 0.813: 97.79,34.29 95.25,34.29 E$144.2 87.63,25.4 | E$109.2 39.37,30.48 20.32,30.48 E$98.2
  Bottom 1.016: E$144.2 v92.71,29.21
S$152  (via drill 0.3 pad 2.54)
  Bottom 1.016: E$94.2 46.99,39.37 41.91,41.91 31.75,41.91 27.94,38.1 E$134.2 v34.29,33.02
S$153
  Bottom 1.016: E$117.2 72.39,39.37 E$63.B 67.31,41.91 49.53,41.91 | E$62.B 22.86,46.99 31.75,46.99 40.64,44.45 46.99,41.91 49.53,41.91 | 49.53,41.91 E$94.3
S$154  (via drill 0.61 pad 6.45)
  other vias: 154.94,50.8
S$155  (via drill 0.61 pad 6.45)
  other vias: 46.99,50.8
S$156  (via drill 0.61 pad 3.81)
  other vias: 119.38,3.81
S$157  (via drill 0.61 pad 3.81)
  other vias: 123.19,3.81
S$158  (via drill 0.61 pad 3.81)
  other vias: 109.22,5.08
S$159  (via drill 0.61 pad 3.81)
  other vias: 113.03,5.08
S$160  (via drill 0.61 pad 3.81)
  other vias: 113.03,8.89
S$161  (via drill 0.61 pad 3.81)
  other vias: 109.22,8.89
S$162
  Bottom 0.813: E$155.A 139.7,16.51 E$157.1
S$163
  Bottom 0.813: E$172.1 160.02,2.54
S$164
  Bottom 0.813: E$142.2 E$175.C E$100.3
S$165
  Bottom 0.813: E$147.2 110.49,33.02 106.68,33.02 E$177.A 102.87,34.29
S$166
  Bottom 0.813: E$178.C 99.06,25.4 104.14,27.94 114.3,27.94 E$179.A E$152.2
S$167
  Bottom 0.61: E$124.A 57.15,24.13 64.77,24.13 67.31,22.86 85.09,22.86 88.9,20.32 92.71,20.32 95.25,16.51 110.49,16.51 111.76,20.32 118.11,20.32 120.65,17.78 124.46,17.78 125.73,21.59 127,24.13 162.56,24.13 163.83,19.05 179.07,19.05 E$115.1
  Bottom 0.813: E$129.1 E$127.A E$124.A 48.26,22.86 E$113.4
S$168  (via drill 0.61 pad 2.54)
  other vias: 5.08,6.35
S$169  (via drill 0.61 pad 2.54)
  other vias: 2.54,6.35
S$170  (via drill 0.61 pad 2.54)
  other vias: 5.08,3.81
S$171  (via drill 0.61 pad 2.54)
  other vias: 2.54,3.81
S$172  (via drill 0.61 pad 2.54)
  other vias: 195.58,5.08
S$173  (via drill 0.61 pad 2.54)
  other vias: 198.12,5.08
S$174  (via drill 0.61 pad 2.54)
  other vias: 195.58,2.54
S$175  (via drill 0.61 pad 2.54)
  other vias: 198.12,2.54
S$176  (via drill 0.3 pad 2.54)
  Bottom 0.813: E$109.1 53.34,27.94 69.85,27.94 71.12,29.21 E$175.A
  Bottom 1.016: E$109.1 44.45,29.21 E$94.1 E$134.1 v39.37,33.02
